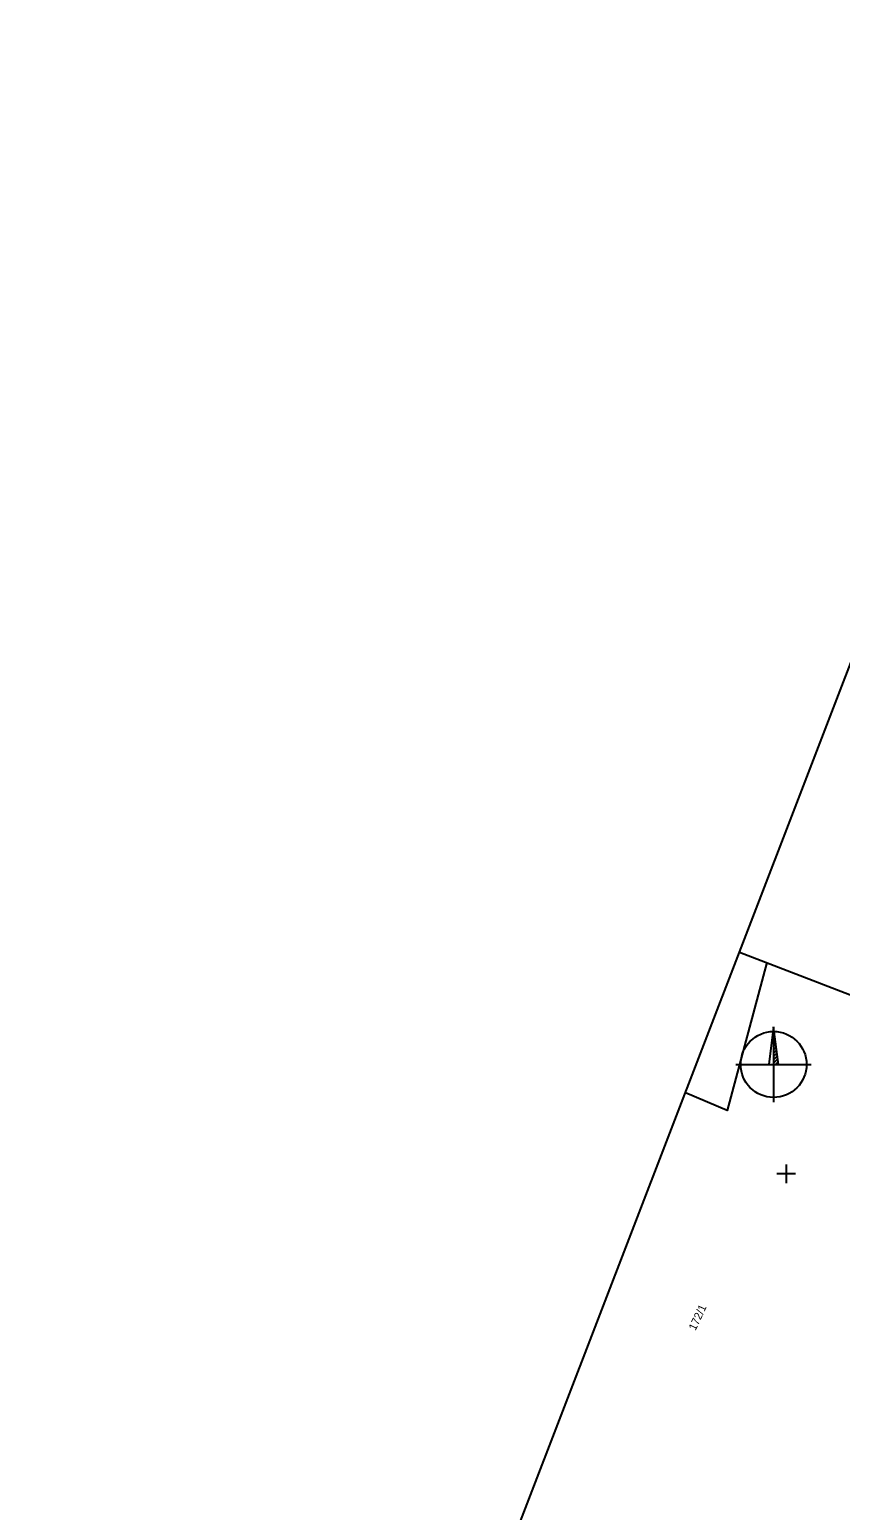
# Model space of a CAD drawing. Extents: x -755061 to -754557, y -1162352 to -1161657.
# Drawn here: x -755060.7 to -754888.5, y -1161971.5 to -1161656.9 of the extents above; entities that cross this region are included whole.
import ezdxf

# ---------------------------------------------------------------- set-up
doc = ezdxf.new("R2010")
doc.units = 0
for name, color, linetype in [('Formát', 7, 'Continuous'), ('Severka', 7, 'Continuous'), ('Síť', 7, 'Continuous'), ('Vrstva 55', 7, 'Continuous'), ('Vrstva 57', 7, 'Continuous')]:
    doc.layers.add(name, color=color, linetype=linetype)

msp = doc.modelspace()

# ---------------------------------------------------------------- linework, layer by layer
at = {"layer": 'Formát'}
msp.add_lwpolyline([(-754909.9, -1161852.87), (-754834.47, -1161656.88), (-754557.29, -1161763.56), (-754632.71, -1161959.54)], dxfattribs=at)
msp.add_lwpolyline([(-754909.9, -1161852.87), (-754632.71, -1161959.54), (-754783.57, -1162351.52), (-755060.75, -1162244.84)], close=True, dxfattribs=at)
at = {"layer": 'Severka'}
for p, q in [((-754902.67, -1161868.75), (-754903.67, -1161876.75)), ((-754902.67, -1161868.75), (-754902.67, -1161884.75)), ((-754902.67, -1161869.39), (-754902.6, -1161869.31)), ((-754902.67, -1161870.09), (-754902.52, -1161869.94)), ((-754902.67, -1161870.8), (-754902.45, -1161870.57)), ((-754902.67, -1161871.51), (-754902.37, -1161871.2)), ((-754902.67, -1161872.21), (-754902.29, -1161871.83)), ((-754902.67, -1161872.92), (-754902.21, -1161872.46)), ((-754902.67, -1161873.63), (-754902.13, -1161873.09)), ((-754902.67, -1161874.34), (-754902.05, -1161873.71)), ((-754902.67, -1161875.04), (-754901.97, -1161874.34)), ((-754902.67, -1161875.75), (-754901.9, -1161874.97)), ((-754902.67, -1161876.46), (-754901.82, -1161875.6)), ((-754902.26, -1161876.75), (-754901.74, -1161876.23)), ((-754910.67, -1161876.75), (-754894.67, -1161876.75))]:
    msp.add_line(p, q, dxfattribs=at)
msp.add_lwpolyline([(-754902.67, -1161868.75), (-754902.67, -1161876.75), (-754901.67, -1161876.75)], close=True, dxfattribs=at)
msp.add_circle((-754902.67, -1161876.75), 7, dxfattribs=at)
at = {"layer": 'Síť'}
for points in [[(-754900, -1161898), (-754900, -1161900), (-754900, -1161902)], [(-754898, -1161900), (-754900, -1161900), (-754902, -1161900)]]:
    msp.add_lwpolyline(points, dxfattribs=at)
at = {"layer": 'Vrstva 55'}
msp.add_lwpolyline([(-754904.1, -1161855.1), (-754912.51, -1161886.53), (-754921.39, -1161882.75)], dxfattribs=at)

# ---------------------------------------------------------------- texts
at = {"layer": 'Vrstva 57'}
msp.add_text('172/1', height=1.7, rotation=65, dxfattribs=at).set_placement((-754919.27, -1161933.42))

doc.saveas('drawing.dxf')
